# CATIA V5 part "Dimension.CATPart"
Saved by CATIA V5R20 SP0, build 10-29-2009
Part number: Part3
Bounding box of the stored display mesh (mm): x -114 to 114, y -62.297 to 84.112, z -35.081 to 39.679
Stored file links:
  J:\카티아자료\수업자료\툴바예제\3 Drafting\Dimension.CATPart
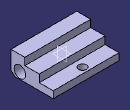
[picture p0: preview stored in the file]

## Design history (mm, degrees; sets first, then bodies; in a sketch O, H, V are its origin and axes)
Body1 (main body)
  Sketch1 on yz-plane, origin (0, 0, 0), H (0, 1, 0), V (0, 0, 1)
    line L1 (-62.297, 39.6785) -> (-14.0597, 39.6785)
    line L2 (-14.0597, 39.6785) -> (-14.0597, 14.7892)
    line L3 (-14.0597, 14.7892) -> (35.7735, 14.7892)
    line L4 (35.7735, 14.7892) -> (35.7735, -11.2722)
    line L5 (35.7735, -11.2722) -> (84.1116, -11.2722)
    line L6 (84.1116, -11.2722) -> (84.1116, -35.081)
    line L7 (84.1116, -35.081) -> (-62.297, -35.081)
    line L8 (-62.297, -35.081) -> (-62.297, 39.6785)
    horizontal: L1 H, L3 H, L5 H, L7 H
    vertical: L2 V, L4 V, L6 V, L8 V
  Pad1: profile Sketch1, direction (1, 0, 0), length 114, mirrored extent
  Sketch2 on face of Pad1 from Sketch1.L5, origin (18.7028, 72.103, -11.2722), H (1, 0, 0), V (0, 1, 0)
    point P1 (-26.3274, -8.1947)
  Hole1: placed by Sketch2, at (-7.6246, 63.9083, -11.2722) direction (0, 0, -1), diameter 27, depth 100
  Sketch3 on end face of Pad1, origin (114, -16.2258, -45.8803), H (0, 1, 0), V (0, 0, 1)
    point P1 (-15.3294, 33.8597)
  Hole2: placed by Sketch3, at (114, -31.5551, -12.0206) direction (-1, 0, 0), diameter 20, depth 301, counterbore diameter 40, counterbore depth 100
  Chamfer1: length 13, angle 45, on edge [face of Pad1 from Sketch1.L7 | face of Pad1 from Sketch1.L8]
